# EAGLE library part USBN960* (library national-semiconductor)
USBN9603/USBN9604 Universal Serial Bus Full Speed Node Controller with Enhanced DMA Support Source: http://www.national.com .. USBN9603.pdf
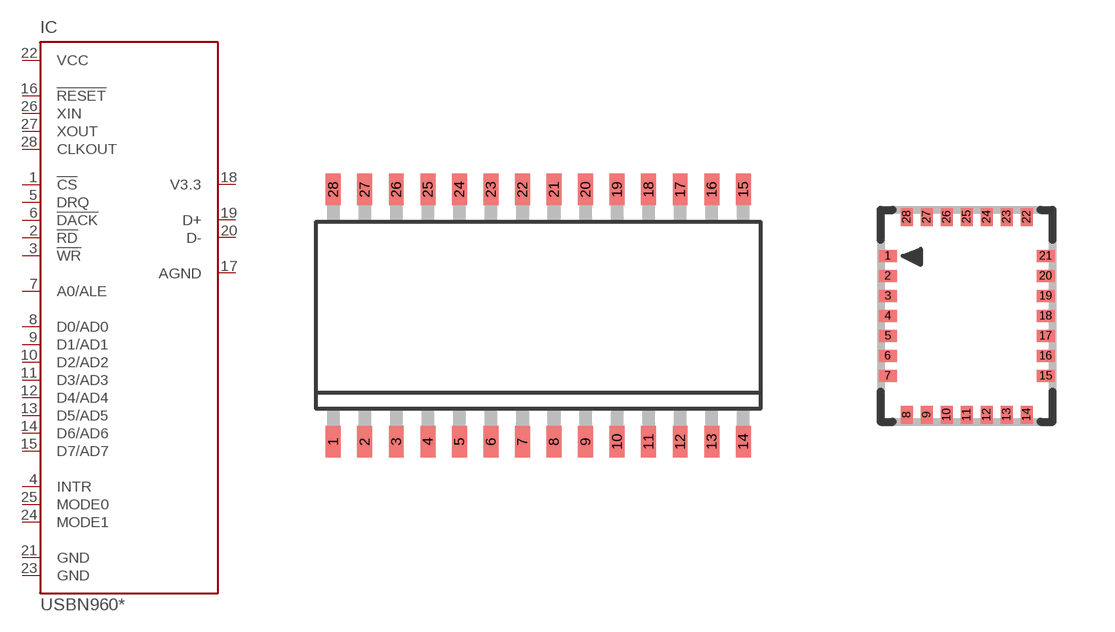
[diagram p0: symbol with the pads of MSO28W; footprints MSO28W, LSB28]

Designator prefix IC

## USBN9603-28M (MF: NATIONAL SEMICONDUCTOR; MPN: USBN9603-28M/NOPB; OC_FARNELL: 1214542; OC_NEWARK: 41K8479), USBN9604-28M (MF: NATIONAL SEMICONDUCTOR; MPN: USBN9604-28M; OC_FARNELL: 1214543; OC_NEWARK: 34C6795)  [MSO28W]
1  !CS  in
2  !RD  in
3  !WR  in
4  INTR  in
5  DRQ  in
6  !DACK  in
7  A0/ALE  in
8  D0/AD0  in
9  D1/AD1  in
10  D2/AD2  in
11  D3/AD3  in
12  D4/AD4  in
13  D5/AD5  in
14  D6/AD6  in
15  D7/AD7  in
16  !RESET  in
17  AGND  pwr
18  V3.3  out
19  D+
20  D-
21  GND  pwr
22  VCC  pwr
23  GND  pwr
24  MODE1  in
25  MODE0  in
26  XIN  in
27  XOUT  out
28  CLKOUT  out

## USBN9603SLB (MPN: USBN9603SLB; OC_FARNELL: unknown; OC_NEWARK: 22M2133), USBN9604SLB (MF: NATIONAL SEMICONDUCTOR; MPN: USBN9604SLB; OC_FARNELL: unknown; OC_NEWARK: 41J8499)  [LSB28]
1  D3/AD3  in
2  D4/AD4  in
3  D5/AD5  in
4  D6/AD6  in
5  D7/AD7  in
6  !RESET  in
7  AGND  pwr
8  V3.3  out
9  D+
10  D-
11  GND  pwr
12  VCC  pwr
13  GND  pwr
14  MODE1  in
15  MODE0  in
16  XIN  in
17  XOUT  out
18  CLKOUT  out
19  !CS  in
20  !RD  in
21  !WR  in
22  INTR  in
23  DRQ  in
24  !DACK  in
25  A0/ALE  in
26  D0/AD0  in
27  D1/AD1  in
28  D2/AD2  in

## Footprint MSO28W (pad centres in mm)
Molded SO Wide Body Package (WM) See NS Package Number M28B Source: http://www.national.com .. USBN9603.pdf
smd 0.6 x 1.27: 1 -8.255,-5.08; 2 -6.985,-5.08; 3 -5.715,-5.08; 4 -4.445,-5.08; 5 -3.175,-5.08; 6 -1.905,-5.08; 7 -0.635,-5.08; 8 0.635,-5.08; 9 1.905,-5.08; 10 3.175,-5.08; 11 4.445,-5.08; 12 5.715,-5.08; 13 6.985,-5.08; 14 8.255,-5.08; 15 8.255,5.08; 16 6.985,5.08; 17 5.715,5.08; 18 4.445,5.08; 19 3.175,5.08; 20 1.905,5.08; 21 0.635,5.08; 22 -0.635,5.08; 23 -1.905,5.08; 24 -3.175,5.08; 25 -4.445,5.08; 26 -5.715,5.08; 27 -6.985,5.08; 28 -8.255,5.08

## Footprint LSB28 (pad centres in mm)
Laminate Substrate Based Package See NS Package Number SLB28AA Source: http://www.national.com .. USBN9603.pdf
smd 0.45 x 0.3: 1 -1.975,1.5; 2 -1.975,1; 3 -1.975,0.5; 4 -1.975,0; 5 -1.975,-0.5; 6 -1.975,-1; 7 -1.975,-1.5; 15 1.975,-1.5; 16 1.975,-1; 17 1.975,-0.5; 18 1.975,0; 19 1.975,0.5; 20 1.975,1; 21 1.975,1.5
smd 0.3 x 0.45: 8 -1.5,-2.475; 9 -1,-2.475; 10 -0.5,-2.475; 11 0,-2.475; 12 0.5,-2.475; 13 1,-2.475; 14 1.5,-2.475; 22 1.5,2.475; 23 1,2.475; 24 0.5,2.475; 25 0,2.475; 26 -0.5,2.475; 27 -1,2.475; 28 -1.5,2.475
